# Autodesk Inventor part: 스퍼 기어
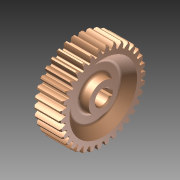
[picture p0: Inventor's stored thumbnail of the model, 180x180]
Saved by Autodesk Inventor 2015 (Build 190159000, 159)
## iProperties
Created: 2026-04
Part Number: 스퍼 기어
Material: 일반
Document SubType Name: Modeling
Designer: User
Density: 1 g/cm^3
Appearance: 기본값
Author: User
Author: jhkim
Creation Date: 2026-03-26
Sending System: Autodesk Inventor 2026
Preprocessor: ST-DEVELOPER v20.1
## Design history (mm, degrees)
node "스퍼 기어1"
node "솔리드1"
node "기준1"
